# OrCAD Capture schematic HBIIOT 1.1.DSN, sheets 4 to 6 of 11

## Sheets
4 PCIe, M.2, RTC: size C; title: PCIE, M.2, RTC, IR
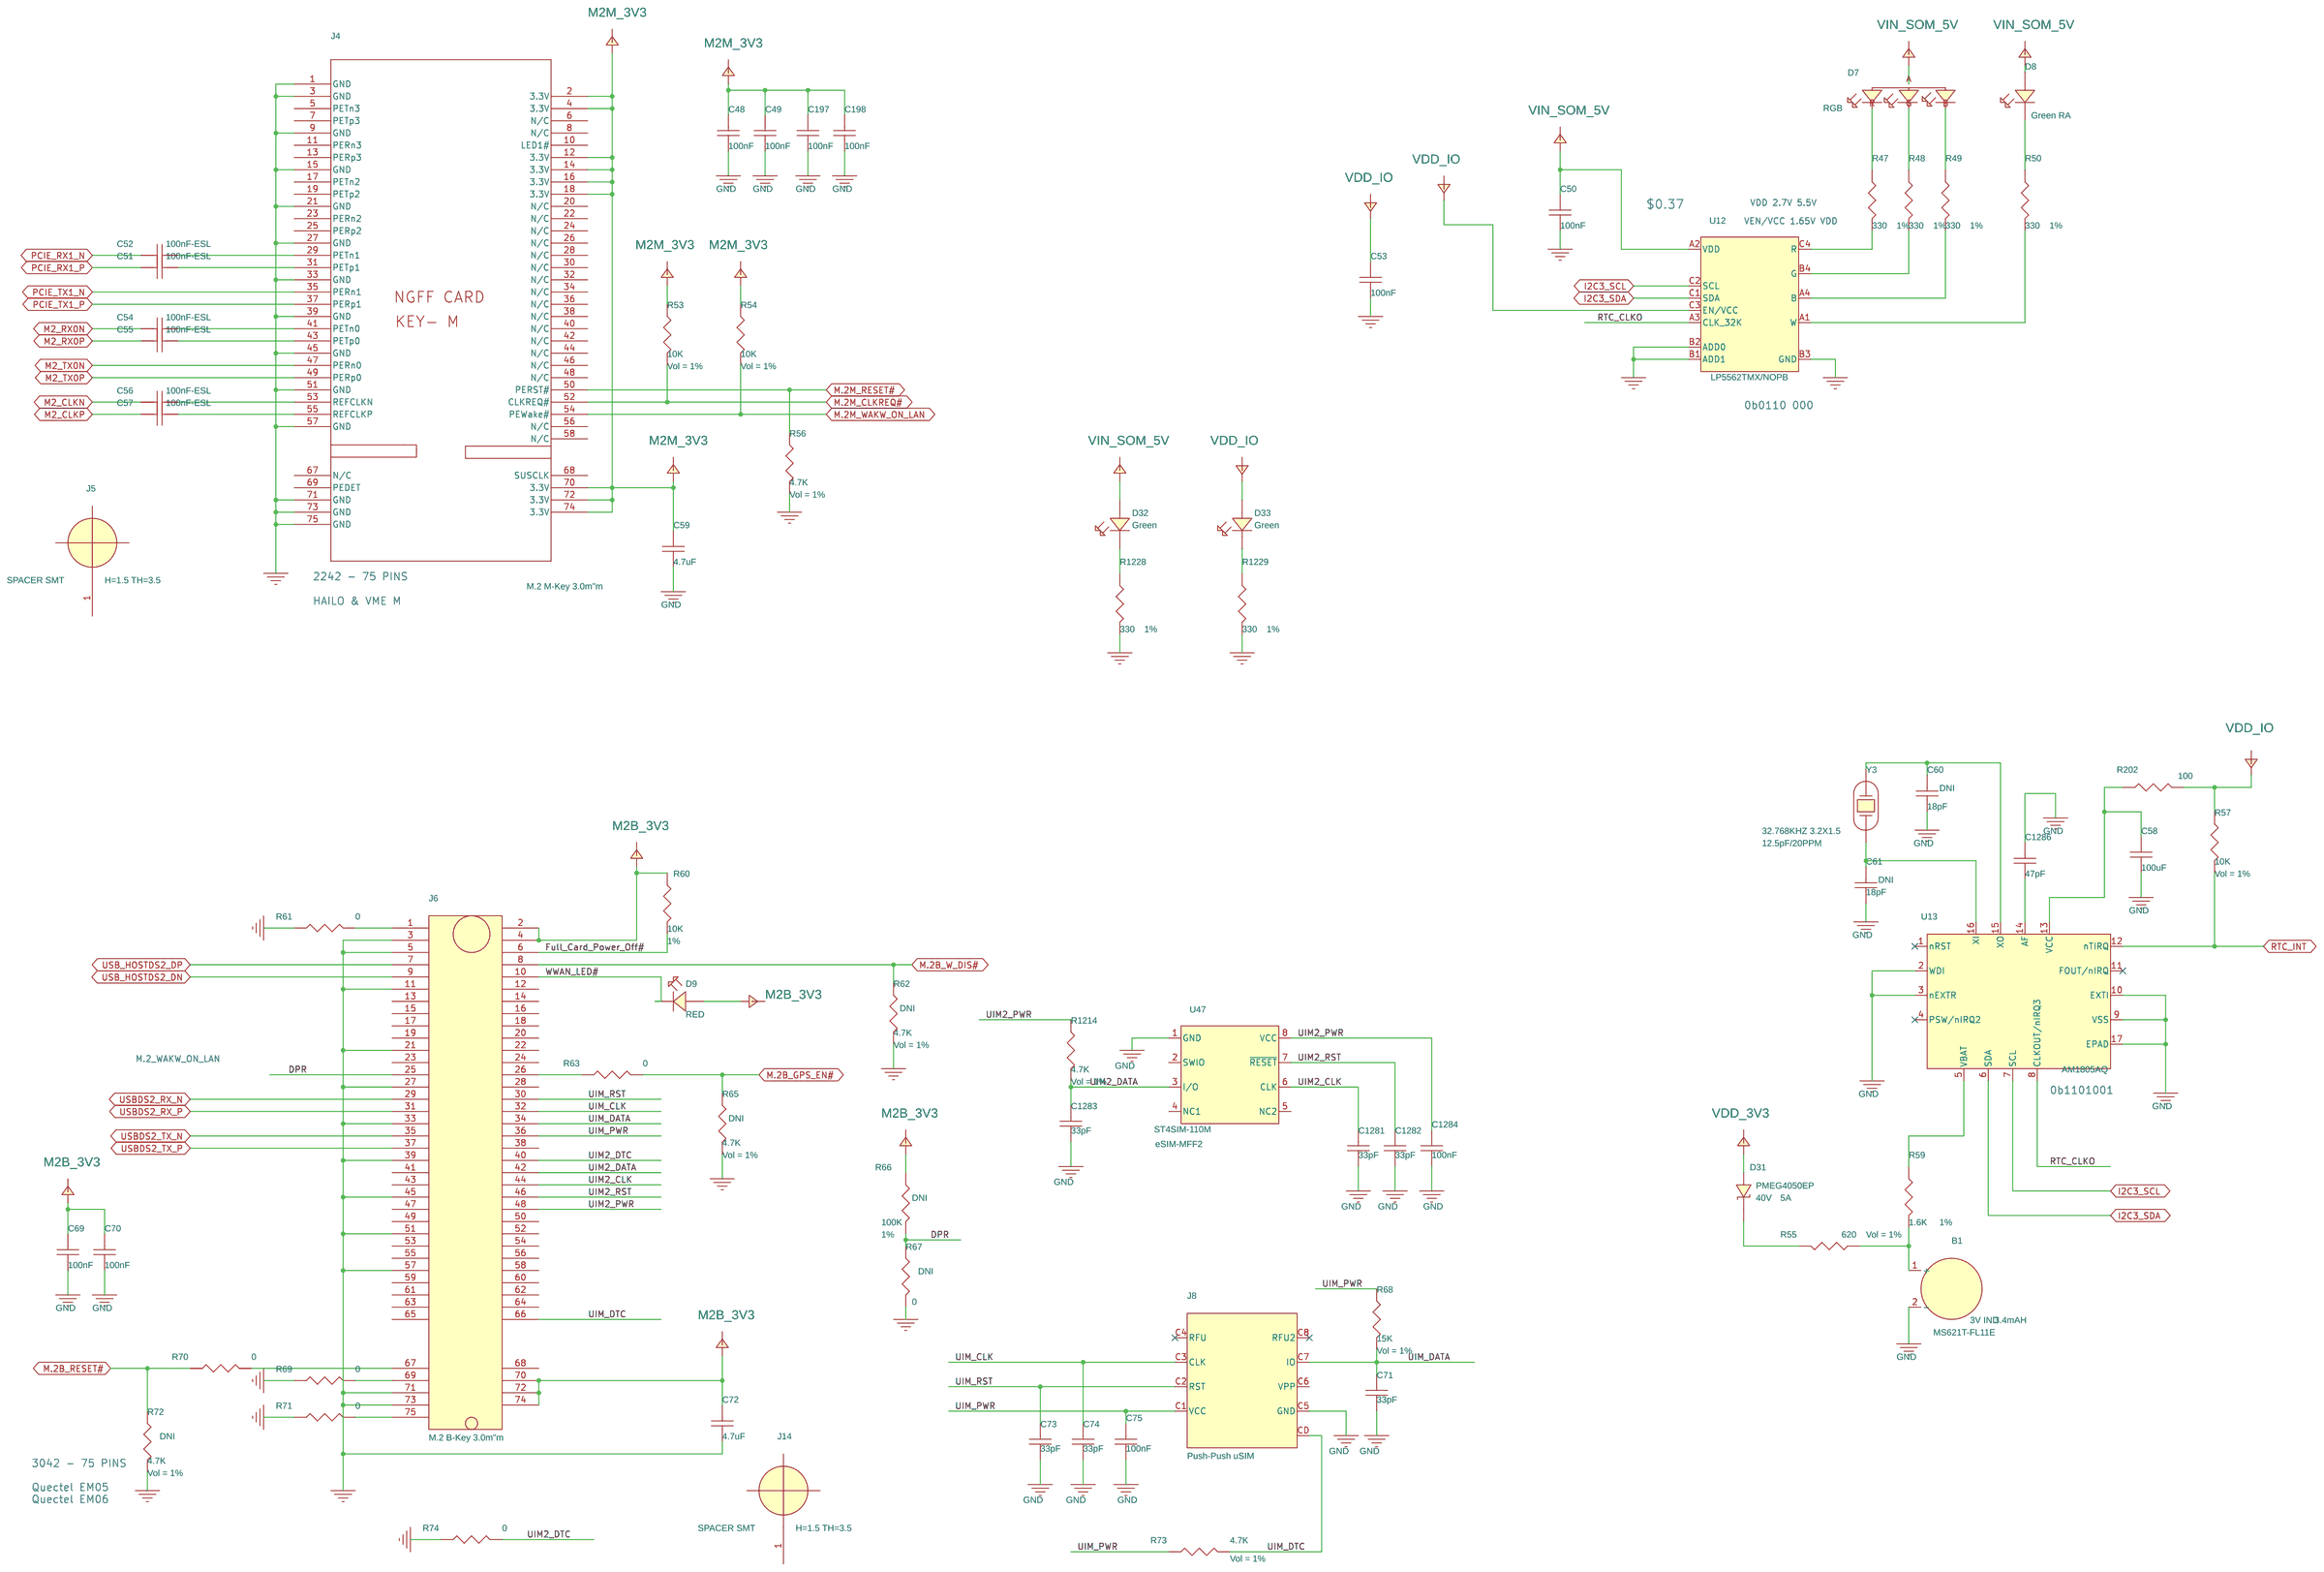
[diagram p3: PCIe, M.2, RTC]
5 Ethernet: size C; title: ETHERNET; rev: 2.4.0
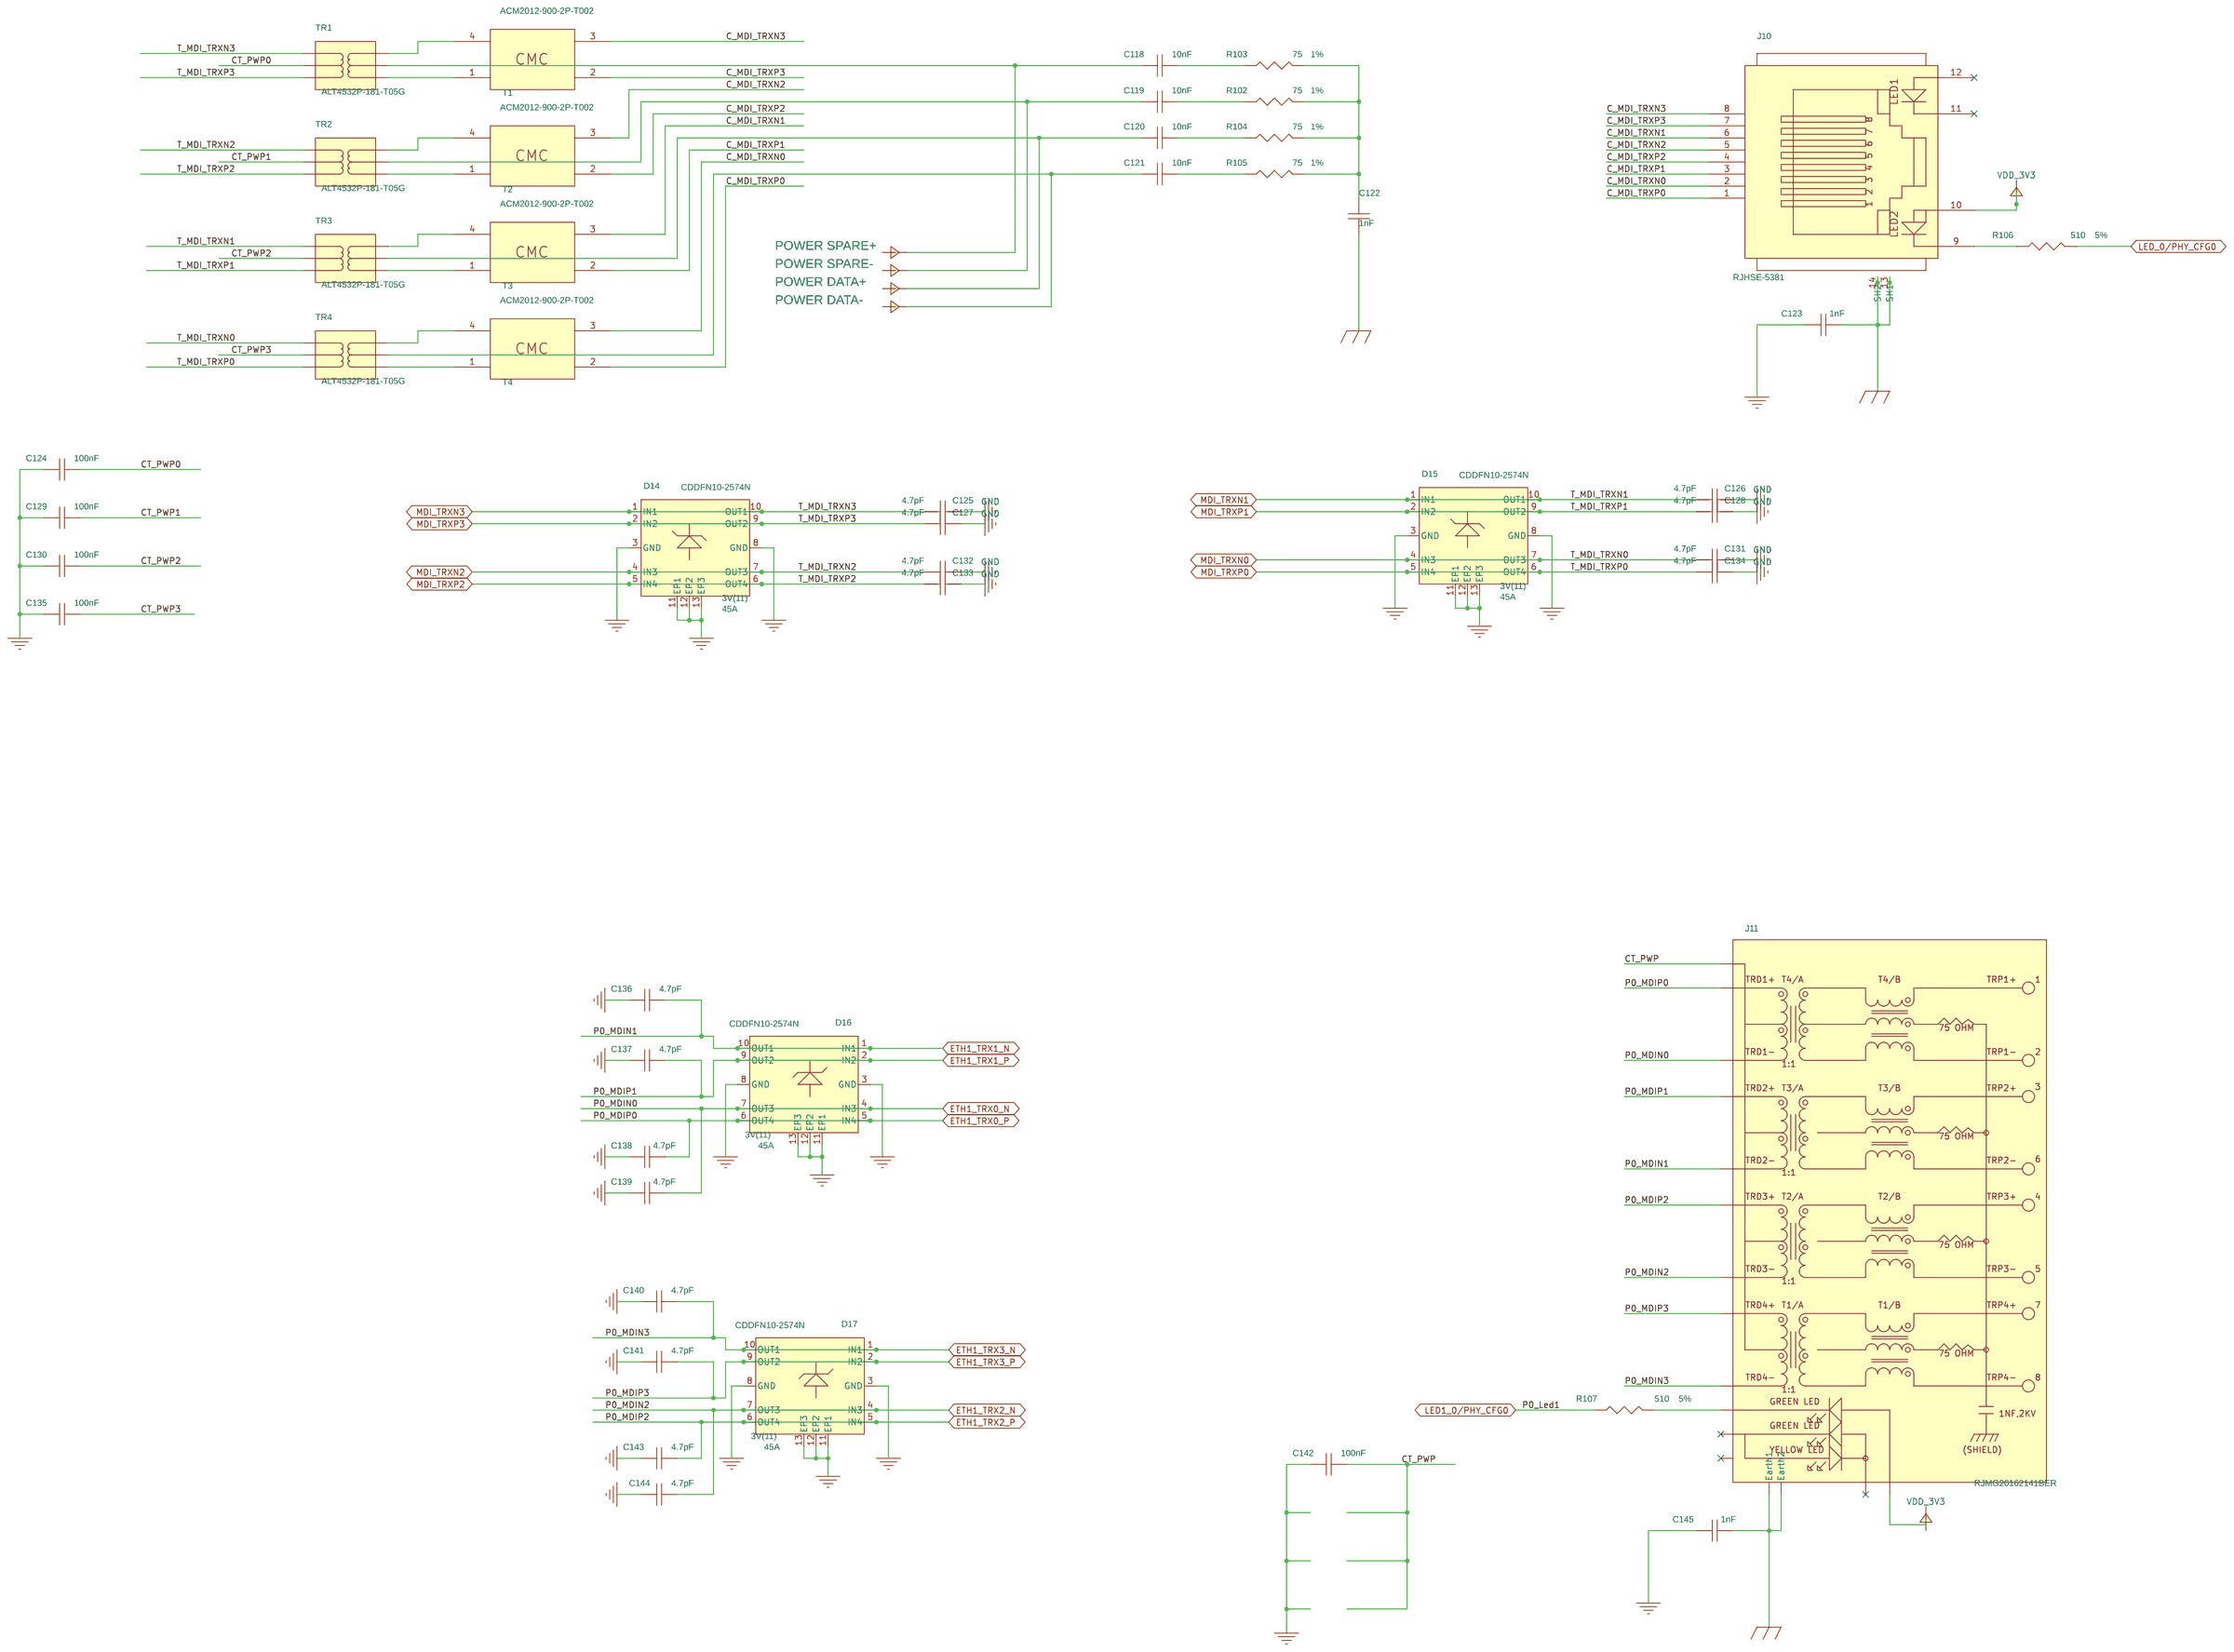
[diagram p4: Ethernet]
6 B-t-B Connectors: size D; title: B-T-B CONNECTORS; rev: 2.4.0
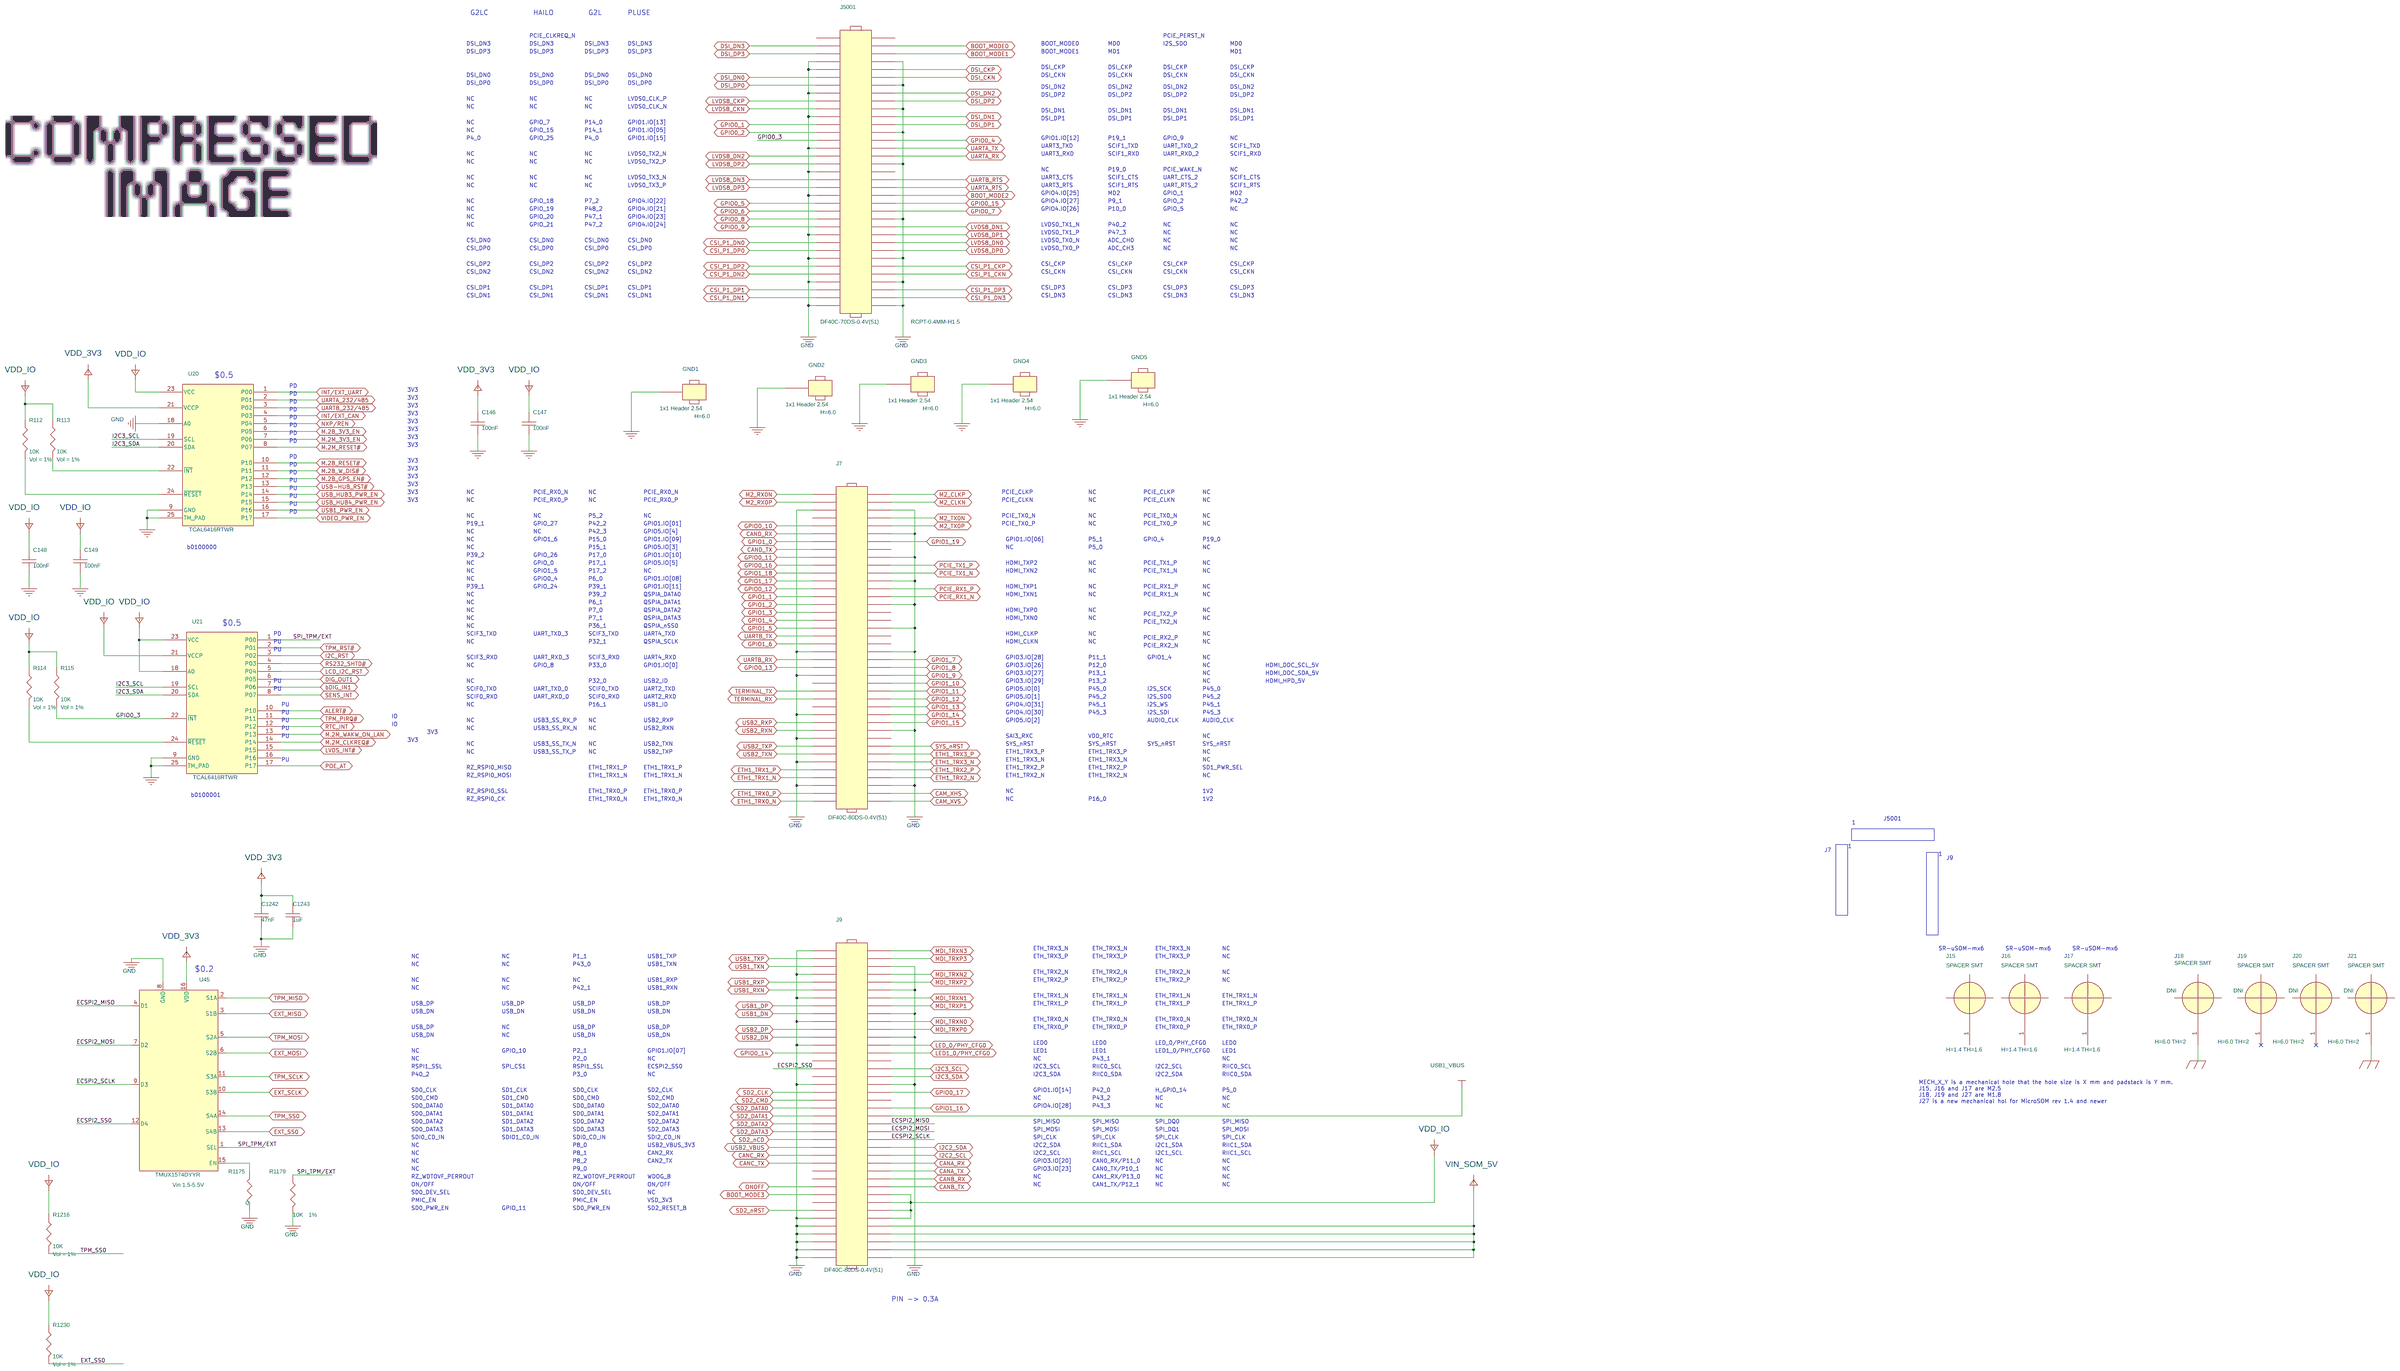
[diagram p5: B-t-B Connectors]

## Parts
sheet B-t-B Connectors
C146  100nF  [C0402]
C147  100nF  [C0402]
C148  100nF  [C0402]
C149  100nF  [C0402]
C1242  47nF  [C0402]
C1243  1uF  [C0402]
GND1  1x1 Header 2.54  [CH31012V200-NH]
GND2  1x1 Header 2.54  [CH31012V200-NH]
GND3  1x1 Header 2.54  [CH31012V200-NH]
GND4  1x1 Header 2.54  [CH31012V200-NH]
GND5  1x1 Header 2.54  [CH31012V200-NH]
J7  DF40C-80DS-0.4V(51)  [DF40C-80DS-0.4V(51)]
J9  DF40C-80DS-0.4V(51)  [DF40C-80DS-0.4V(51)]
J15  SPACER SMT
J16  SPACER SMT
J17  SPACER SMT
J18  SPACER SMT
J19  SPACER SMT
J20  SPACER SMT
J21  SPACER SMT
J5001  DF40C-70DS-0.4V(51)  [DF40C-70DS-0.4V(51)]
R112  10K  [R0402]
R113  10K  [R0402]
R114  10K  [R0402]
R115  10K  [R0402]
R1175  0  [R0402]
R1179  10K  [R0402]
R1216  10K  [R0402]
R1230  10K  [R0402]
U20  TCAL6416RTWR  [TCAL6416RTWR]
U21  TCAL6416RTWR  [TCAL6416RTWR]
U45  TMUX1574DYYR  [TMUX1574DYYR]
sheet Ethernet
C118  10nF  [C0402]
C119  10nF  [C0402]
C120  10nF  [C0402]
C121  10nF  [C0402]
C122  1nF  [C1206]
C123  1nF  [C1206]
C124  100nF  [C0402]
C125  4.7pF  [C0402]
C126  4.7pF  [C0402]
C127  4.7pF  [C0402]
C128  4.7pF  [C0402]
C129  100nF  [C0402]
C130  100nF  [C0402]
C131  4.7pF  [C0402]
C132  4.7pF  [C0402]
C133  4.7pF  [C0402]
C134  4.7pF  [C0402]
C135  100nF  [C0402]
C136  4.7pF  [C0402]
C137  4.7pF  [C0402]
C138  4.7pF  [C0402]
C139  4.7pF  [C0402]
C140  4.7pF  [C0402]
C141  4.7pF  [C0402]
C142  100nF  [C0402]
C143  4.7pF  [C0402]
C144  4.7pF  [C0402]
C145  1nF  [C1206]
D14  CDDFN10-2574N  [CDDFN10-2574N]
D15  CDDFN10-2574N  [CDDFN10-2574N]
D16  CDDFN10-2574N  [CDDFN10-2574N]
D17  CDDFN10-2574N  [CDDFN10-2574N]
J10  RJHSE-5381  [RJHSE-5381]
J11  RJMG20162141BER  [RJMG20162141BER]
R102  75  [R0402]
R103  75  [R0402]
R104  75  [R0402]
R105  75  [R0402]
R106  510  [R0402]
R107  510  [R0402]
T1  ACM2012-900-2P-T002  [ACM2012-900-2P-T002]
T2  ACM2012-900-2P-T002  [ACM2012-900-2P-T002]
T3  ACM2012-900-2P-T002  [ACM2012-900-2P-T002]
T4  ACM2012-900-2P-T002  [ACM2012-900-2P-T002]
TR1  ALT4532P-181-T05G  [ALT4532P-181-T05G]
TR2  ALT4532P-181-T05G  [ALT4532P-181-T05G]
TR3  ALT4532P-181-T05G  [ALT4532P-181-T05G]
TR4  ALT4532P-181-T05G  [ALT4532P-181-T05G]
sheet PCIe, M.2, RTC
B1  MS621T-FL11E  [MS621T-FL11E]
C48  100nF  [C0402]
C49  100nF  [C0402]
C50  100nF  [C0402]
C51  100nF-ESL  [C0402]
C52  100nF-ESL  [C0402]
C53  100nF  [C0402]
C54  100nF-ESL  [C0402]
C55  100nF-ESL  [C0402]
C56  100nF-ESL  [C0402]
C57  100nF-ESL  [C0402]
C58  100uF  [C1210]
C59  4.7uF  [C0603]
C60  18pF  [C0402]
C61  18pF  [C0402]
C69  100nF  [C0402]
C70  100nF  [C0402]
C71  33pF  [C0402]
C72  4.7uF  [C0603]
C73  33pF  [C0402]
C74  33pF  [C0402]
C75  100nF  [C0402]
C197  100nF  [C0402]
C198  100nF  [C0402]
C1281  33pF  [C0402]
C1282  33pF  [C0402]
C1283  33pF  [C0402]
C1284  100nF  [C0402]
C1286  47pF  [C0402]
D7  RGB  [LRTBR48G]
D8  Green RA  [APA2106CGCK]
D9  RED  [1SA0603S11A0CB01]
D31  PMEG4050EP  [PMEG4050EP]
D32  Green  [1SA0603G32A0CB01]
D33  Green  [1SA0603G32A0CB01]
J4  M.2 M-Key 3.0m"m  [AS0BC21-S30BM-7H]
J5  SPACER SMT
J6  M.2 B-Key 3.0m"m  [AS0BC21-S30BB-7H]
J8  Push-Push uSIM  [SIM7100-6-1-15-00-A]
J14  SPACER SMT
R47  330  [R0402]
R48  330  [R0402]
R49  330  [R0402]
R50  330  [R0402]
R53  10K  [R0402]
R54  10K  [R0402]
R55  620  [R0402]
R56  4.7K  [R0402]
R57  10K  [R0402]
R59  1.6K  [R0402]
R60  10K  [R0402]
R61  0  [R0402]
R62  4.7K  [R0402]
R63  0  [R0402]
R65  4.7K  [R0402]
R66  100K  [R0402]
R67  0  [R0402]
R68  15K  [R0402]
R69  0  [R0402]
R70  0  [R0402]
R71  0  [R0402]
R72  4.7K  [R0402]
R73  4.7K  [R0402]
R74  0  [R0402]
R202  100  [R0603]
R1214  4.7K  [R0402]
R1228  330  [R0402]
R1229  330  [R0402]
U12  LP5562TMX/NOPB  [LP5562TMX/NOPB]
U13  AM1805AQ  [AM1805AQ]
U47  ST4SIM-110M  [ST4SIM-110M]
Y3  32.768KHZ 3.2X1.5  [NX3215SA32.768K-STD-MUA-4]

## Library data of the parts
C75 C146-C149 C1284 = CAP_NP1: CAP CER 0.1uF ±10% 16V X7R 0402; Digikey P/N: 1276-1001-1-ND; Manufacturer: Samsung Electro-Mechanics; Part Num#: CL05B104KO5NNNC; Rating: 16V; SolidRun P/N: CA20013; Vol: 10%
C1242 = CAP_NP1: CHIP CAP 47nF 6.3V 0402 X7R; Manufacturer: Samsung Electro-Mechanics; Part Num#: CL05B473MQQNNNE; Rating: 6.3V; SolidRun P/N: CA20012; Vol: 10%
C1243 = CAP_NP1: CAP CER 1uF ±10% 6.3V X7R 0402; Digikey P/N: 1276-1513-1-ND; Manufacturer: Samsung Electro-Mechanics; Part Num#: CL05B105KQ5NQNC; Rating: 6.3V; SolidRun P/N: CA20132; Vol: 10%
GND1-GND5 = J-HEADER-1x1: CH31 Series 2.54mm(.100") Single Row Pin Headers- 1 x 1 V TH; Manufacturer: cvilux; SolidRun P/N: CO00517; Vol: H=6.0; Datasheet: https://www.cvilux.com/uploads/catalog/p283%20CH31.pdf
J7 J9 = J-DF40C-80DS-0.4V(51): CONN RCPT 80POS 0.4MM SMD GOLD Without reinforcing metal fitting 1.5mm; Category : CON-HEADER; Digikey P/N: H11633TR-ND; Manufacturer: Hirose Electric Co Ltd; SolidRun P/N: CO00017; VOL: RCPT-0.4MM-H1.5; Datasheet: https://www.hirose.com/product/download/?distributor=digikey&type=2d&lang=en&num=DF40C-80DS-0.4V(51)
J15-J17 = SPACER_SMT: SPACER H=1.4MM  TH=1.6MM - Used as imx6-uSOM spacer; Category : MECH-SPACER; Manufacturer: A-Link; Part Num#: N0143416A; SolidRun P/N: MCH0007; Vol: H=1.4 TH=1.6; Datasheet: http://www.alink.com.tw/smt%20fastener%20standard%20parts.html
J18-J21 = SPACER_SMT: 6mm PCB spacer to enclsoure (used in HummingBoard); ASSEMBLY: DNI; BOM_IGNORE: TRUE; Category : MECH-SPACER; Digikey P/N: 732-7103-2-ND; Manufacturer: Wurth Elektronik; Part Num#: WE 977-406-024-3R; SolidRun P/N: MCH0009; Vol: H=6.0 TH=2; Datasheet: http://katalog.we-online.de/em/datasheet/9774060243R.pdf
J5001 = J-DF40C-70DS-0.4V(51): CONN RCPT 70POS 0.4MM SMD GOLD Without reinforcing metal fitting 1.5 mm; Category : CON-HEADER; Digikey P/N: H11631TR-ND; Manufacturer: Hirose Electric Co Ltd; SolidRun P/N: CO00511; VOL: RCPT-0.4MM-H1.5; Datasheet: https://www.hirose.com/product/download/?distributor=digikey&type=2d&lang=en&num=DF40C-70DS-0.4V(51)
R53 R54 R57 R112-R115 R1216 R1230 = RES1: RES SMD 10K OHM 1% 1/16W 0402; Digikey P/N: 311-10.0KLRCT-ND; Manufacturer: YAGEO; Part Num#: RC0402FR-0710KL; Rating: 1/16W; SolidRun P/N: RE20013; Vol: 1%
R1175 = RES1: RES SMD 0 OHM JUMPER 1/16W 0402; Digikey P/N: 311-0.0JRCT-ND; Manufacturer: YAGEO; Part Num#: RC0402JR-070RL; Rating: 1/16W; SolidRun P/N: RE20009
R60 R1179 = RES1: RES SMD 10K OHM 1% 1/16W 0402; Category : Resistors (Size: 0402); Digikey P/N: 311-10.0KLRCT-ND; Manufacturer: YAGEO; Part Num#: RC0402FR-0710KL; Rating: 1/16W; SolidRun P/N: RE20013; Vol: 1%
U20 U21 = IC-TCAL6416-WQFN: I/O Expander 16 I²C 100 kHz 24-WQFN (4x4), voltage trans, Open Drain/Push/Pull; Digikey P/N: 296-TCAL6416RTWRTR-ND; Manufacturer: Texas Instruments; SolidRun P/N: IC01927; Datasheet: https://www.ti.com/lit/ds/symlink/tcal6416.pdf
U45 = IC-TMUX1574DYYR: 4 Circuit IC Switch 2:1 4.5Ohm 16-SOT-23-THIN; Digikey P/N: 296-TMUX1574DYYRTR-ND; Manufacturer: Texas Instruments; SolidRun P/N: IC01637; Vol: Vin 1.5-5.5V; Datasheet: https://www.ti.com/general/docs/suppproductinfo.tsp?distId=10&gotoUrl=https%3A%2F%2Fwww.ti.com%2Flit%2Fgpn%2Ftmux1574
C118-C121 = CAP_NP1: CAP CER 10000PF 100V X7R 0402; Category : Capacitors (Size: 0402); Digikey P/N: 13-CC0402KRX7R0BB103TR-ND; Manufacturer: YAGEO; Part Num#: CC0402KRX7R0BB103; Rating: 100V; SolidRun P/N: CA20837; Vol: 10%
C122 C123 C145 = CAP_NP1: CAP CER 1nF ±10% 1KV X7R 1206; Category : Capacitors (Size: 1206); Digikey P/N: 490-3494-2-ND; Manufacturer: Murata Electronics North America; Part Num#: GRM31BR73A102KW01L; Rating: 1KV; SolidRun P/N: CA50002; Vol: 10%
C124 C129 C130 C135 C142 = CAP_NP1: CAP CER 0.1uF ±10% 50V X7R 0402; Category : Capacitors (Size: 0402); Digikey P/N: 490-10700-1-ND; Manufacturer: Murata Electronics North America; Part Num#: GRM155R71H104KE14D; Rating: 50V; SolidRun P/N: CA20147; Vol: 10%
C125-C128 C131-C134 C136-C141 C143 C144 = CAP_NP1: CAP CER 4.7pF ±0.05pF 50V C0G/NP0 0402; Category : Capacitors (Size: 0402); Digikey P/N: 311-1033-1-ND; Manufacturer: Murata Electronics North America; Part Num#: GJM1555C1H4R7WB01D; Rating: 50V; SolidRun P/N: CA20807; Vol: 1%
D14-D17 = D-CDDFN10-2574N: TVS Diode Array, 4 Channel, Ipp=45A, Vclump=11V, 1.7pF@1MHz, 10-DFN (3x2), -55°C ~ 85°C (TA); Category: DI-TVS; Digikey P/N: CDDFN10-2574NCT-ND; Manufacturer: Bourns Inc.; Rating: 45A; SolidRun P/N: DI00271; Vol: 3V(11); Datasheet: https://www.bourns.com/docs/product-datasheets/cddfn10-2574n.pdf
J10 = J-RJHSE538x: CONN MOD JACK 8P8C R/A SHIELDED; Category : CON-ETH/RJ; Digikey P/N: RJHSE-5381-ND; Manufacturer: Amphenol Commercial Products; SolidRun P/N: CO00654; VOL: JACK 8P8C R/A SHIELDED; Datasheet: https://www.amphenolcanada.com/ProductSearch/drawings/AC/RJHSE538X.pdf
J11 = J-RJMG20162141BER-FCI: CONN MAGJACK 1PORT 1000 BASE-T; Category : CON-ETH/RJ; Digikey P/N: RJMG20162141BER-ND; Manufacturer: Amphenol Commercial Products; SolidRun P/N: CO00673; Vol: MAGJACK; Datasheet: https://www.amphenolcanada.com/ProductSearch/Drawings/AC/RJMG20162141BER.PDF
R102-R105 = RES1: RES SMD 75 OHM 1% 1/16W 0402; Category : Resistors (Size: 0402); Digikey P/N: 311-75.0LRCT-ND; Manufacturer: YAGEO; Part Num#: RC0402FR-0775RL; Rating: 1/16W; SolidRun P/N: RE20401; Vol: 1%
R106 R107 = RES1: RES SMD 510 OHM 5% 1/16W 0402; Category : Resistors (Size: 0402); Digikey P/N: 311-510JRCT-ND; Manufacturer: YAGEO; Part Num#: RC0402JR-07510RL; Rating: 1/16W; SolidRun P/N: RE20022; Vol: 5%
T1-T4 = CMC: 2 Line Common Mode Choke Surface Mount 90 Ohms @ 100MHz 400mA DCR 190mOhm; Digikey P/N: 445-2207-2-ND; Manufacturer: TDK Corporation; Rating: 0.4A; SolidRun P/N: IN00162; Vol: 90Ohm/100M; Datasheet: https://product.tdk.com/info/en/catalog/datasheets/cmf_commercial_signal_acm2012_en.pdf?ref_disty=digikey
TR1-TR4 = ALT4532M: PULSE TRANSFORMERS FOR LAN INTER, 180µH LAN Pulse Transformer 1CT:1CT Surface Mount POE+ suppport; Digikey P/N: 445-175377-2-ND; Manufacturer: TDK Corporation; SolidRun P/N: IC01873; Vol: POE+; Datasheet: https://product.tdk.com/en/system/files?file=dam/doc/product/transformer/transformer/lan/catalog/trans_alt4532p_en.pdf
B1 = BAT-MS621FE: Coin, 6.8mm 3 V Lithium Battery Rechargeable (Secondary) 3mAh IND (Was MS614SE FL28E); Category : Battery-RCH; Digikey P/N: 728-1080-ND; Manufacturer: Seiko Instruments; Rating: 3.4mAH; SolidRun P/N: BT00007; Vol: 3V IND; Datasheet: https://www.seiko-instruments.de/fileadmin/Editors/COMP/PDF/MicroBattery_catalogue_E_2018A_forWeb.pdf
C48 C49 C69 C70 C197 C198 = CAP_NP1: CAP CER 0.1uF ±10% 16V X7R 0402; Category : Capacitors (Size: 0603); Digikey P/N: 1276-1001-1-ND; Manufacturer: Samsung Electro-Mechanics; Part Num#: CL05B104KO5NNNC; Rating: 16V; SolidRun P/N: CA20013; Vol: 10%
C50 C53 = CAP_NP1: CAP CER 0.1uF ±10% 16V X7R 0402; Category : Capacitors (Size: 0402); Digikey P/N: 1276-1001-1-ND; Manufacturer: Samsung Electro-Mechanics; Part Num#: CL05B104KO5NNNC; Rating: 16V; SolidRun P/N: CA20013; Vol: 10%
C51 C52 C54-C57 = CAP_NP1: CAP CER 0.1uF ±10% 25V X7R 0402; Category : Capacitors (Size: 0402); Manufacturer: CAPAX; Part Num#: 0402X104K250SNT; Rating: 25V; SolidRun P/N: CA20090; Vol: 10%
C58 = CAP_NP1: CAP CER 100uF ±20% 16V X5R 1210; Category : Capacitors (Size: 0603); Digikey P/N: 311-2052-1-ND; Manufacturer: YAGEO; Part Num#: CC1210MKX5R7BB107; Rating: 16V; SolidRun P/N: CA60008; Vol: 20%
C59 C72 = CAP_NP1: CAP CER 4.7uF ±10% 6.3V X5R; Category : Capacitors (Size: 0603); Digikey P/N: 1276-1045-2-ND; Manufacturer: Samsung Electro-Mechanics; Part Num#: CL10A475KQ8NNNC; Rating: 6.3V; SolidRun P/N: CA30003; Vol: 10%
C60 C61 = CAP_NP1: CAP CER 18pF ±1% 50V C0G/NPO 0402; ASSEMBLY: DNI; BOM_IGNORE: TRUE; Category : Capacitors (Size: 0402); Digikey P/N: 311-1643-1-ND; Manufacturer: YAGEO; Part Num#: CC0402FRNPO9BN180; Rating: 50V; SolidRun P/N: CA20017; Vol: 1%
C71 C73 C74 C1281-C1283 = CAP_NP1: CAP CER 33pF ±5% 50V C0G/NP0 0402; Digikey P/N: 490-3220-1-ND; Manufacturer: Murata Electronics North America; Part Num#: GRM1555C1H330JZ01D; Rating: 50V; SolidRun P/N: CA20135; Vol: 5%
C1286 = CAP_NP1: CAP CER 47pF ±5% 50V C0G/NP0 0402; Category : Capacitors (Size: 0402); Digikey P/N: 490-1287-6-ND; Manufacturer: Murata Electronics North America; Part Num#: GRM1555C1H470JZ01D; Rating: 50V; SolidRun P/N: CA20144; Vol: 5%
D7 = LED-RGB: Red, Green, Blue (RGB) 623nm Red, 530nm Green, 471nm Blue LED Indication - Discrete 1.95V Red, 2.7V Green, 2.7V Blue 0404 (1010 Metric); Digikey P/N: 475-3483-2-ND; Manufacturer: OSRAM Opto Semiconductors Inc.; Part Num#: LRTB R48G-P9Q7-1+R7S5-26+N5P-68-ZB; Rating: 0.01/0.005/0.005A; SolidRun P/N: DI00259; Vol: 1.95/2.7/2.7; Datasheet: https://dammedia.osram.info/media/resource/hires/osram-dam-4307982/LRTB%20R48G.pdf
D8 = LED: LED 2.1X0.6MM 570NM GRN RA SMD; Category: DI-LED; Digikey P/N: 754-1057-2-ND; Manufacturer: Kingbright Corp; Rating: 0.02A; SolidRun P/N: DI00250; Vol: 2.1V; Datasheet: http://www.kingbrightusa.com/images/catalog/SPEC/APA2106CGCK.pdf
D9 = LED: Indication LED 0603 - Red; Category : DI-LED; Manufacturer: BRIGHTEK; Rating: 0.02A; SolidRun P/N: DI00007; Vol: 2V
D31 = Diode-STK-OLD: DIODE SCHOTTKY 40V 5A CFP5; Digikey P/N: 1727-5842-2-ND; Manufacturer: Nexperia USA Inc.; Rating: 5A; SolidRun P/N: DI00286; Vol: 40V; Datasheet: https://assets.nexperia.com/documents/data-sheet/PMEG4050EP.pdf
D32 D33 = LED: Indication LED 0603 - Green; Manufacturer: BRIGHTEK; Rating: 0.02A; SolidRun P/N: DI00008; Vol: 2V
J4 = M-NGFF_M.2_KEY_M: NGFF M.2 SSD M-Key 3.0 m"m connector; Manufacturer: Foxconn; SolidRun P/N: CO00514; Datasheet: http://www.fit-foxconn.com/Product/ProductDetail?topClassID=&&PN=AS0BC21-S30BM-7H
J5 J14 = SPACER_SMT: 1.5mm metal spacer for M.2.5 connector 3.5mm / 5.1mm (3.7mm / 6.0mm hole); Category: MECH-SPACER; Category : MECHANICAL PARTS; Digikey P/N: 732-7068-2-ND; Manufacturer: Wurth Elektronik; Part Num#: WE 977-401-515-1R; SolidRun P/N: MCH0008; Vol: H=1.5 TH=3.5; Datasheet: http://katalog.we-online.de/em/datasheet/9774015151R.pdf
J6 = M-NGFF_M.2: NGFF M.2 SSD connector with 2242 matching hole - 3.0H Key B; Category: CON-PCIe/SATA/M.2; Category : CON-PCIe/SATA/M.2; Manufacturer: Foxconn; SolidRun P/N: CO00595; Datasheet: http://www.fit-foxconn.com/Product/ProductDetail?topClassID=&&PN=AS0BC21-S30BB-7H
J8 = J-uSIM_CARD_HOLDER_x_8: Micro SIM Card Connector - Push-Push Type 6 or 8 Pin, SMT, 1.50mm Profile (6-pin); Digikey P/N: 2073-SIM7100-6-1-15-00-ATR-ND; Manufacturer: GCT; SolidRun P/N: CO00569; Datasheet: https://gct.co/files/drawings/sim7100.pdf
R47-R50 R1228 R1229 = RES1: RES SMD 330 OHM 1% 1/16W 0402; Category : Resistors (Size: 0402); Digikey P/N: 311-330LRCT-ND; Manufacturer: YAGEO; Part Num#: RC0402FR-07330RL; Rating: 1/16W; SolidRun P/N: RE20209; Vol: 1%
R55 = RES1: RES SMD 620 OHM 1% 1/16W 0402; Digikey P/N: 311-620LRCT-ND; Manufacturer: YAGEO; Part Num#: RC0402FR-07620RL; Rating: 1/16W; SolidRun P/N: RE20403; Vol: 1%
R56 R1214 = RES1: RES SMD 4.7K OHM 1% 1/16W 0402; Digikey P/N: 311-4.7KLRCT-ND; Manufacturer: YAGEO; Part Num#: RC0402FR-074K7L; Rating: 1/16W; SolidRun P/N: RE20497; Vol: 1%
R59 = RES1: RES SMD 1.6K OHM 1% 1/16W 0402; Category : Resistors (Size: 0402); Digikey P/N: YAG3045CT-ND; Manufacturer: YAGEO; Part Num#: RC0402FR-071K6L; Rating: 1/16W; SolidRun P/N: RE20030; Vol: 1%
R61 R63 R69-R71 R74 = RES1: RES SMD 0 OHM JUMPER 1/16W 0402; Category : Resistors (Size: 0402); Digikey P/N: 311-0.0JRCT-ND; Manufacturer: YAGEO; Part Num#: RC0402JR-070RL; Rating: 1/16W; SolidRun P/N: RE20009
R62 R65 R72 = RES1: RES SMD 4.7K OHM 1% 1/16W 0402; ASSEMBLY: DNI; BOM_IGNORE: TRUE; Digikey P/N: 311-4.7KLRCT-ND; Manufacturer: YAGEO; Part Num#: RC0402FR-074K7L; Rating: 1/16W; SolidRun P/N: RE20497; Vol: 1%
R66 = RES1: RES SMD 100K OHM 1% 1/16W 0402; ASSEMBLY: DNI; BOM_IGNORE: TRUE; Category : Resistors (Size: 0402); Digikey P/N: 311-100KLRCT-ND; Manufacturer: YAGEO; Part Num#: RC0402FR-07100KL; Rating: 1/16W; SolidRun P/N: RE20482; Vol: 1%
R67 = RES1: RES SMD 0 OHM JUMPER 1/16W 0402; ASSEMBLY: DNI; BOM_IGNORE: TRUE; Category : Resistors (Size: 0402); Digikey P/N: 311-0.0JRCT-ND; Manufacturer: YAGEO; Part Num#: RC0402JR-070RL; Rating: 1/16W; SolidRun P/N: RE20009
R68 = RES1: RES SMD 15K OHM 1% 1/16W 0402; Digikey P/N: 311-15.0KLRCT-ND; Manufacturer: YAGEO; Part Num#: RC0402FR-0715KL; Rating: 1/16W; SolidRun P/N: RE20100; Vol: 1%
R73 = RES1: RES SMD 4.7K OHM 1% 1/16W 0402; Category : Resistors (Size: 0402); Digikey P/N: 311-4.7KLRCT-ND; Manufacturer: YAGEO; Part Num#: RC0402FR-074K7L; Rating: 1/16W; SolidRun P/N: RE20497; Vol: 1%
R202 = RES1: RES SMD 100 OHM 5% 1/4W 0603; Digikey P/N: RHM100DTR-ND; Manufacturer: Rohm Semiconductor; Part Num#: ESR03EZPJ101; Rating: 1/4W; SolidRun P/N: RE30040; Vol: 5%
U12 = IC-LP5562: LED Driver IC 4 Output Linear I²C Dimming 25.5mA 12-DSBGA; Digikey P/N: 296-39061-2-ND; Manufacturer: Texas Instruments; SolidRun P/N: IC01926; Datasheet: https://www.ti.com/general/docs/suppproductinfo.tsp?distId=10&gotoUrl=https%3A%2F%2Fwww.ti.com%2Flit%2Fgpn%2Flp5562
U13 = IC-AM1805: REAL-TIME CLOCK WITH POWER MANAG; Category : IC-RTC; Digikey P/N: 1822-1006-2-ND; Manufacturer: Ambiq Micro, Inc.; SolidRun P/N: IC01186; Datasheet: http://ambiqmicro.com/wp-content/uploads/2016/11/am18x5_data_sheet_ds0003v1p2.pdf
U47 = IC-eSIM-MFF2: eSIM system-on-chip solution for secure M2M industrial applications; Manufacturer: STMicroelectronics; SolidRun P/N: IC01945; Vol: eSIM-MFF2; Datasheet: https://www.st.com/resource/en/data_brief/st4sim-110m.pdf
Y3 = XTAL-2P: XTAL 32.768KHZ 12.5PF 20PPM 3.2X1.5MM SM; Category : OC-CRYSTAL; Manufacturer: NDK; Rating: 12.5pF/20PPM; SolidRun P/N: OC00001; Datasheet: http://www.ndk.com/images/products/catalog/c_NX3215SA_e.pdf

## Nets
GND: B1.2(-) C48.2 C49.2 C50.2 C53.2 C58.2 C59.2 C60.2 C61.2 C69.2 C70.2 C71.2 C72.2 C73.2 C74.2 C75.2 C123.2 C124.1 C125.2 C126.2 C127.2 C128.2 C129.1 C130.1 C131.2 C132.2 C133.2 C134.2 C135.1 C136.2 C137.2 C138.2 C139.2 C140.2 C141.2 C142.1 C143.2 C144.2 C145.2 C146.2 C147.2 C148.2 C149.2 C197.2 C198.2 C1242.2 C1243.2 C1281.2 C1282.2 C1283.2 C1284.2 C1286.1 D14.3(GND) D14.8(GND) D14.11(EP1) D14.12(EP2) D14.13(EP3) D15.3(GND) D15.8(GND) D15.11(EP1) D15.12(EP2) D15.13(EP3) D16.3(GND) D16.8(GND) D16.11(EP1) D16.12(EP2) D16.13(EP3) D17.3(GND) D17.8(GND) D17.11(EP1) D17.12(EP2) D17.13(EP3) GND1.1 GND2.1 GND3.1 GND4.1 GND5.1 J4.1(GND) J4.3(GND) J4.9(GND) J4.15(GND) J4.21(GND) J4.27(GND) J4.33(GND) J4.39(GND) J4.45(GND) J4.51(GND) J4.57(GND) J4.71(GND) J4.73(GND) J4.75(GND) J6.3 J6.5 J6.11 J6.21 J6.27 J6.33 J6.39 J6.45 J6.51 J6.57 J6.71 J6.73 J7.5 J7.6 J7.11 J7.17 J7.23 J7.29 J7.35 J7.41 J7.42 J7.48 J7.58 J7.61 J7.64 J7.70 J7.75 J7.76 J8.C5(GND) J9.2 J9.5 J9.8 J9.11 J9.14 J9.17 J9.20 J9.23 J9.26 J9.35 J9.36 J9.70 J9.72 J9.74 J9.76 J9.78 J9.80 J5001.7 J5001.8 J5001.10 J5001.13 J5001.16 J5001.19 J5001.22 J5001.25 J5001.30 J5001.33 J5001.36 J5001.42 J5001.47 J5001.52 J5001.57 J5001.58 J5001.63 J5001.64 J5001.69 J5001.70 R56.2 R61.1 R62.2 R65.2 R67.2 R69.1 R71.1 R72.2 R74.1 R1175.2 R1179.2 R1228.2 R1229.2 U12.B1(ADD1) U12.B2(ADD0) U12.B3(GND) U13.2(WDI) U13.3(nEXTR) U13.9(VSS) U13.10(EXTI) U13.17(EPAD) U20.9(GND) U20.18(A0) U20.25(TM_PAD) U21.9(GND) U21.25(TM_PAD) U45.8(GND) U47.1(GND) ; also on sheet 1 2 3 7 8 9 11
GNDC: C122.2 C123.1 C145.1 J10.13(SH1) J10.14(SH2) J11.SH1(Earth1) J11.SH2(Earth2) J18.1 J21.1 ; also on sheet 2 3
VDD_3V3: C146.1 C1242.1 C1243.1 D31.2(ANODE) J10.10 J11.13 U20.21(VCCP) U45.16(VDD) ; also on sheet 1 2 3 7 8 11
VDD_IO: C53.1 C147.1 C148.1 C149.1 D33.A J9.63 J9.65 J9.67 J9.69 R57.1 R112.1 R113.1 R114.1 R115.1 R202.2 R1216.1 R1230.1 U12.C3(EN/VCC) U20.23(VCC) U21.18(A0) U21.21(VCCP) U21.23(VCC) ; also on sheet 1 2 7 8 9 11
ALERT#: U21.10(P10) ; also on sheet 9
bDIG_IN1: U21.7(P06) ; also on sheet 11
BOOT_MODE0: J5001.3 ; also on sheet 2
BOOT_MODE1: J5001.5 ; also on sheet 2
BOOT_MODE2: J5001.41 ; also on sheet 2
BOOT_MODE3: J9.64 ; also on sheet 2
C_MDI_TRXN0: J10.2 T4.3
C_MDI_TRXN1: J10.6 T3.3
C_MDI_TRXN2: J10.5 T2.3
C_MDI_TRXN3: J10.8 T1.3
C_MDI_TRXP0: J10.1 T4.2
C_MDI_TRXP1: J10.3 T3.2
C_MDI_TRXP2: J10.4 T2.2
C_MDI_TRXP3: J10.7 T1.2
CAM_XHS: J7.77 ; also on sheet 7
CAM_XVS: J7.79 ; also on sheet 7
CANA_RX: J9.55 ; also on sheet 11
CANA_TX: J9.57 ; also on sheet 11
CANB_RX: J9.59 ; also on sheet 11
CANB_TX: J9.61 ; also on sheet 11
CANC_RX: J9.54 ; also on sheet 11
CANC_TX: J9.56 ; also on sheet 11
CAND_RX: J7.12 ; also on sheet 11
CAND_TX: J7.16 ; also on sheet 11
CSI_P1_CKN: J5001.61 ; also on sheet 7
CSI_P1_CKP: J5001.59 ; also on sheet 7
CSI_P1_DN0: J5001.54 ; also on sheet 7
CSI_P1_DN1: J5001.68 ; also on sheet 7
CSI_P1_DN2: J5001.62 ; also on sheet 7
CSI_P1_DN3: J5001.67 ; also on sheet 7
CSI_P1_DP0: J5001.56 ; also on sheet 7
CSI_P1_DP1: J5001.66 ; also on sheet 7
CSI_P1_DP2: J5001.60 ; also on sheet 7
CSI_P1_DP3: J5001.65 ; also on sheet 7
CT_PWP: C142.2 J11.P2
CT_PWP0: C124.2 TR1.6
CT_PWP1: C129.2 TR2.6
CT_PWP2: C130.2 TR3.6
CT_PWP3: C135.2 TR4.6
DIG_OUT1: U21.6(P05) ; also on sheet 11
DPR: J6.25 R66.2 R67.1
DSI_CKN: J5001.11 ; also on sheet 7
DSI_CKP: J5001.9 ; also on sheet 7
DSI_DN0: J5001.12 ; also on sheet 7
DSI_DN1: J5001.21 ; also on sheet 7
DSI_DN2: J5001.15 ; also on sheet 7
DSI_DN3: J5001.4 ; also on sheet 7
DSI_DP0: J5001.14 ; also on sheet 7
DSI_DP1: J5001.23 ; also on sheet 7
DSI_DP2: J5001.17 ; also on sheet 7
DSI_DP3: J5001.6 ; also on sheet 7
ECSPI2_MISO: J9.45 U45.4(D1)
ECSPI2_MOSI: J9.47 U45.7(D2)
ECSPI2_SCLK: J9.49 U45.9(D3)
ECSPI2_SS0: J9.32 U45.12(D4)
ETH1_TRX0_N: C139.1 D16.4(IN3) D16.7(OUT3) J7.80 J11.P10
ETH1_TRX0_P: C138.1 D16.5(IN4) D16.6(OUT4) J7.78 J11.P9
ETH1_TRX1_N: C136.1 D16.1(IN1) D16.10(OUT1) J7.74 J11.P8
ETH1_TRX1_P: C137.1 D16.2(IN2) D16.9(OUT2) J7.72 J11.P7
ETH1_TRX2_N: C144.1 D17.4(IN3) D17.7(OUT3) J7.73 J11.P6
ETH1_TRX2_P: C143.1 D17.5(IN4) D17.6(OUT4) J7.71 J11.P5
ETH1_TRX3_N: C140.1 D17.1(IN1) D17.10(OUT1) J7.69 J11.P4
ETH1_TRX3_P: C141.1 D17.2(IN2) D17.9(OUT2) J7.67 J11.P3
EXT_MISO: U45.3(S1B) ; also on sheet 7
EXT_MOSI: U45.6(S2B) ; also on sheet 7
EXT_SCLK: U45.10(S3B) ; also on sheet 7
EXT_SS0: R1230.2 U45.13(S4B) ; also on sheet 7
Full_Card_Power_Off#: J6.6 R60.2
GPIO0_1: J5001.24 ; also on sheet 7
GPIO0_2: J5001.26 ; also on sheet 7
GPIO0_3: J5001.28 R115.2 U21.22(~{INT})
GPIO0_4: J5001.27 ; also on sheet 7
GPIO0_5: J5001.44 ; also on sheet 7
GPIO0_6: J5001.46 ; also on sheet 7
GPIO0_7: J5001.45 ; also on sheet 7
GPIO0_8: J5001.48 ; also on sheet 7
GPIO0_9: J5001.50 ; also on sheet 7
GPIO0_10: J7.10 ; also on sheet 7
GPIO0_11: J7.18 ; also on sheet 7
GPIO0_12: J7.26 ; also on sheet 7
GPIO0_13: J7.46 ; also on sheet 7
GPIO0_14: J9.28 ; also on sheet 7
GPIO0_15: J5001.43 ; also on sheet 7
GPIO0_16: J7.20 ; also on sheet 7
GPIO0_17: J9.37 ; also on sheet 7
GPIO1_0: J7.14 ; also on sheet 7
GPIO1_1: J7.28 ; also on sheet 7
GPIO1_2: J7.30 ; also on sheet 7
GPIO1_3: J7.32 ; also on sheet 7
GPIO1_4: J7.34 ; also on sheet 7
GPIO1_5: J7.36 ; also on sheet 7
GPIO1_6: J7.40 ; also on sheet 7
GPIO1_7: J7.43 ; also on sheet 7
GPIO1_8: J7.45 ; also on sheet 7
GPIO1_9: J7.47 ; also on sheet 7
GPIO1_10: J7.49 ; also on sheet 7
GPIO1_11: J7.51 ; also on sheet 7
GPIO1_12: J7.53 ; also on sheet 7
GPIO1_13: J7.55 ; also on sheet 7
GPIO1_14: J7.57 ; also on sheet 7
GPIO1_15: J7.59 ; also on sheet 7
GPIO1_16: J9.41 ; also on sheet 7
GPIO1_17: J7.24 ; also on sheet 7
GPIO1_18: J7.22 ; also on sheet 7
GPIO1_19: J7.13 ; also on sheet 7
I2C2_SCL: J9.53 ; also on sheet 3 7
I2C2_SDA: J9.51 ; also on sheet 3 7
I2C3_SCL: J9.31 U12.C2(SCL) U13.7(SCL) U20.19(SCL) U21.19(SCL) ; also on sheet 2 7 8 9
I2C3_SDA: J9.33 U12.C1(SDA) U13.6(SDA) U20.20(SDA) U21.20(SDA) ; also on sheet 2 7 8 9
I2C_RST: U21.3(P02) ; also on sheet 7
INT/EXT_CAN: U20.4(P03) ; also on sheet 11
INT/EXT_UART: U20.1(P00) ; also on sheet 11
LCD_I2C_RST: U21.5(P04) ; also on sheet 7
LED1_0/PHY_CFG0: J9.27 R107.1
LED_0/PHY_CFG0: J9.25 R106.2
LVDS8_CKN: J5001.20 ; also on sheet 7
LVDS8_CKP: J5001.18 ; also on sheet 7
LVDS8_DN0: J5001.53 ; also on sheet 7
LVDS8_DN1: J5001.49 ; also on sheet 7
LVDS8_DN2: J5001.32 ; also on sheet 7
LVDS8_DN3: J5001.38 ; also on sheet 7
LVDS8_DP0: J5001.55 ; also on sheet 7
LVDS8_DP1: J5001.51 ; also on sheet 7
LVDS8_DP2: J5001.34 ; also on sheet 7
LVDS8_DP3: J5001.40 ; also on sheet 7
LVDS_INT#: U21.15(P15) ; also on sheet 7
M2_CLKN: C56.1 J7.3
M2_CLKP: C57.1 J7.1
M2_RX0N: C54.1 J7.2
M2_RX0P: C55.1 J7.4
M2_TX0N: J4.47(PERn0) J7.7
M2_TX0P: J4.49(PERp0) J7.9
M2B_3V3: C69.1 C70.1 C72.1 D9.A J6.2 J6.4 J6.70 J6.72 J6.74 R60.1 R66.1 ; also on sheet 1
M2M_3V3: C48.1 C49.1 C59.1 C197.1 C198.1 J4.2(3.3V) J4.4(3.3V) J4.12(3.3V) J4.14(3.3V) J4.16(3.3V) J4.18(3.3V) J4.70(3.3V) J4.72(3.3V) J4.74(3.3V) R53.1 R54.1 ; also on sheet 1
M.2B_3V3_EN: U20.6(P05) ; also on sheet 1
M.2B_GPS_EN#: R63.2 R65.1 U20.12(P12)
M.2B_RESET#: R70.1 R72.1 U20.10(P10)
M.2B_W_DIS#: J6.8 R62.1 U20.11(P11)
M.2M_3V3_EN: U20.7(P06) ; also on sheet 1
M.2M_CLKREQ#: J4.52(CLKREQ#) R53.2 U21.14(P14)
M.2M_RESET#: J4.50(PERST#) R56.1 U20.8(P07)
M.2M_WAKW_ON_LAN: J4.54(PEWake#) R54.2 U21.13(P13)
MDI_TRXN0: C131.1 D15.4(IN3) D15.7(OUT3) J9.19 TR4.1
MDI_TRXN1: C126.1 D15.1(IN1) D15.10(OUT1) J9.13 TR3.1
MDI_TRXN2: C132.1 D14.4(IN3) D14.7(OUT3) J9.7 TR2.1
MDI_TRXN3: C125.1 D14.1(IN1) D14.10(OUT1) J9.1 TR1.1
MDI_TRXP0: C134.1 D15.5(IN4) D15.6(OUT4) J9.21 TR4.2
MDI_TRXP1: C128.1 D15.2(IN2) D15.9(OUT2) J9.15 TR3.2
MDI_TRXP2: C133.1 D14.5(IN4) D14.6(OUT4) J9.9 TR2.2
MDI_TRXP3: C127.1 D14.2(IN2) D14.9(OUT2) J9.3 TR1.2
NXP/REN: U20.5(P04) ; also on sheet 11
ONOFF: J9.62 ; also on sheet 2
PCIE_RX1_N: C52.1 J7.27
PCIE_RX1_P: C51.1 J7.25
PCIE_TX1_N: J4.35(PERn1) J7.21
PCIE_TX1_P: J4.37(PERp1) J7.19
POE_AT: U21.17(P17) ; also on sheet 1
Power Data+: C120.1 TR3.3 ; also on sheet 1
Power Data-: C121.1 TR4.3 ; also on sheet 1
Power Spare+: C118.1 TR1.3 ; also on sheet 1
Power Spare-: C119.1 TR2.3 ; also on sheet 1
RS232_SHTD#: U21.4(P03) ; also on sheet 11
RTC_CLKO: U12.A3(CLK_32K) U13.8(CLKOUT/nIRQ3)
RTC_INT: R57.2 U13.12(nTIRQ) U21.12(P12)
SD2_CLK: J9.38 ; also on sheet 2
SD2_CMD: J9.40 ; also on sheet 2
SD2_DATA0: J9.42 ; also on sheet 2
SD2_DATA1: J9.44 ; also on sheet 2
SD2_DATA2: J9.46 ; also on sheet 2
SD2_DATA3: J9.48 ; also on sheet 2
SD2_nCD: J9.50 ; also on sheet 2
SD2_nRST: J9.68 ; also on sheet 2
SENS_INT: U21.8(P07) ; also on sheet 8
SPI_TPM/EXT: R1179.1 U21.1(P00) U45.1(SEL)
SYS_nRST: J7.65 ; also on sheet 2
TERMINAL_RX: J7.54 ; also on sheet 2
TERMINAL_TX: J7.52 ; also on sheet 2
TPM_MISO: U45.2(S1A) ; also on sheet 2
TPM_MOSI: U45.5(S2A) ; also on sheet 2
TPM_PIRQ#: U21.11(P11) ; also on sheet 2
TPM_RST#: U21.2(P01) ; also on sheet 2
TPM_SCLK: U45.11(S3A) ; also on sheet 2
TPM_SS0: R1216.2 U45.14(S4A) ; also on sheet 2
UARTA_232/485: U20.2(P01) ; also on sheet 11
UARTA_RTS: J5001.39 ; also on sheet 7 11
UARTA_RX: J5001.31 ; also on sheet 11
UARTA_TX: J5001.29 ; also on sheet 11
UARTB_232/485: U20.3(P02) ; also on sheet 11
UARTB_RTS: J5001.37 ; also on sheet 7 11
UARTB_RX: J7.44 ; also on sheet 11
UARTB_TX: J7.38 ; also on sheet 11
UIM2_CLK: C1281.1 J6.44 U47.6(CLK)
UIM2_DATA: C1283.1 J6.42 R1214.2 U47.3(I/O)
UIM2_DTC: J6.40 R74.2
UIM2_PWR: C1284.1 J6.48 R1214.1 U47.8(VCC)
UIM2_RST: C1282.1 J6.46 U47.7(~{RESET})
UIM_CLK: C74.1 J6.32 J8.C3(CLK)
UIM_DATA: C71.1 J6.34 J8.C7(IO) R68.2
UIM_DTC: J6.66 J8.CD R73.2
UIM_PWR: C75.1 J6.36 J8.C1(VCC) R68.1 R73.1
UIM_RST: C73.1 J6.30 J8.C2(RST)
USB1_DN: J9.18 ; also on sheet 3
USB1_DP: J9.16 ; also on sheet 3
USB1_PWR_EN: U20.16(P16) ; also on sheet 3
USB1_RXN: J9.12 ; also on sheet 3
USB1_RXP: J9.10 ; also on sheet 3
USB1_TXN: J9.6 ; also on sheet 3
USB1_TXP: J9.4 ; also on sheet 3
USB1_VBUS: J9.43 ; also on sheet 3
USB2_DN: J9.24 ; also on sheet 3
USB2_DP: J9.22 ; also on sheet 3
USB2_RXN: J7.62 ; also on sheet 3
USB2_RXP: J7.60 ; also on sheet 3
USB2_TXN: J7.68 ; also on sheet 3
USB2_TXP: J7.66 ; also on sheet 3
USB2_VBUS: J9.52 ; also on sheet 3
USB-HUB_RST#: U20.13(P13) ; also on sheet 3
USB_5V0: C50.1 D7.A D8.A D32.A J9.71 J9.73 J9.75 J9.77 J9.79 U12.A2(VDD) ; also on sheet 1 3 7 11
USB_HOSTDS2_DN: J6.9 ; also on sheet 3
USB_HOSTDS2_DP: J6.7 ; also on sheet 3
USB_HUB3_PWR_EN: U20.14(P14) ; also on sheet 3
USB_HUB4_PWR_EN: U20.15(P15) ; also on sheet 3
USBDS2_RX_N: J6.29 ; also on sheet 3
USBDS2_RX_P: J6.31 ; also on sheet 3
USBDS2_TX_N: J6.35 ; also on sheet 3
USBDS2_TX_P: J6.37 ; also on sheet 3
VIDEO_PWR_EN: U20.17(P17) ; also on sheet 1
WWAN_LED#: D9.C J6.10
N949648: J11.14 R107.2
N18120079: J6.1 R61.2
N18120959: J6.69 R69.2
N18121129: J6.75 R71.2
N18121548: J6.26 R63.1
N18121564: J6.67 R70.2
N18446433: T1.4 TR1.5
N18446493: C118.2 R103.1
N18446495: C122.1 R102.2 R103.2 R104.2 R105.2
N18446501: T1.1 TR1.4
N18446555: C119.2 R102.1
N18446657: T2.4 TR2.5
N18446671: C120.2 R104.1
N18446738: T2.1 TR2.4
N18446750: C121.2 R105.1
N18446829: T3.4 TR3.5
N18446855: T3.1 TR3.4
N18446918: T4.4 TR4.5
N18446941: T4.1 TR4.4
N18447504: J10.9 R106.1
N18590703: C54.2 J4.41(PETn0)
N18590707: C55.2 J4.43(PETp0)
N18590807: C56.2 J4.53(REFCLKN)
N18590811: C57.2 J4.55(REFCLKP)
N18759599: D7.R R47.1
N18759601: D7.G R48.1
N18759603: D7.B R49.1
N18759605: D8.C R50.1
N18759711: R47.2 U12.C4(R)
N18759713: R48.2 U12.B4(G)
N18759715: R49.2 U12.A4(B)
N18759717: R50.2 U12.A1(W)
N18960531: R113.2 U20.22(~{INT})
N18960536: R112.2 U20.24(~{RESET})
N18961727: R114.2 U21.24(~{RESET})
N19529002: C52.2 J4.29(PETn1)
N19529051: C51.2 J4.31(PETp1)
N19565072: R1175.1 U45.15(EN)
N19725768: C60.1 U13.15(XO) Y3.2
N19725841: C58.1 R202.1 U13.13(VCC)
N19725861: C61.1 U13.16(XI) Y3.1
N19725923: C1286.2 U13.14(AF)
N19726053: R59.1 U13.5(VBAT)
N19726104: B1.1(+) R55.1 R59.2
N19730045: D31.1(CATHODE) R55.2
N20168326: D32.C R1228.1
N20168519: D33.C R1229.1

Not connected (* = marked no-connect by the designer): J4 5(PETn3) 6(N/C) 7(PETp3) 8(N/C) 10(LED1#) 11(PERn3) 13(PERp3) 17(PETn2) 19(PETp2) 20(N/C) 22(N/C) 23(PERn2) 24(N/C) 25(PERp2) 26(N/C) 28(N/C) 30(N/C) 32(N/C) 34(N/C) 36(N/C) 38(N/C) 40(N/C) 42(N/C) 44(N/C) 46(N/C) 48(N/C) 56(N/C) 58(N/C) 67(N/C) 68(SUSCLK) 69(PEDET); J5 1; J6 12 13 14 15 16 17 18 19 20 22 23 24 28 38 41 43 47 49 50 52 53 54 55 56 58 59 60 61 62 63 64 65 68; J7 8 15 31 33 37 39 50 56 63; J8 C4(RFU)* C6(VPP) C8(RFU2)*; J9 29 30 34 39 58 60 66; J10 11* 12*; J11 11* 12* P1*; J14 1; J15 1; J16 1; J17 1; J19 1*; J20 1*; J5001 1 2 35; U13 1(nRST)* 4(PSW/nIRQ2)* 11(FOUT/nIRQ)*; U21 16(P16); U47 2(SWIO) 4(NC1) 5(NC2)

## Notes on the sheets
sheet 4
- $0.37
- VDD 2.7V 5.5V
- VEN/VCC 1.65V VDD
- 0b0110 000
- 2242 - 75 PINS
- HAILO & VME M
- M.2_WAKW_ON_LAN
- 0b1101001
- 3042 - 75 PINS
  Quectel EM05
  Quectel EM06
sheet 6
- G2LC
- HAILO
- G2L
- PLUSE
- PCIE_CLKREQ_N
- PCIE_PERST_N
- DSI_DN3
- DSI_DN3
- DSI_DN3
- DSI_DN3
- BOOT_MODE0
- MD0
- I2S_SDO
- MD0
- DSI_DP3
- DSI_DP3
- DSI_DP3
- DSI_DP3
- BOOT_MODE1
- MD1
- MD1
- DSI_CKP
- DSI_CKP
- DSI_CKP
- DSI_CKP
- DSI_DN0
- DSI_DN0
- DSI_DN0
- DSI_DN0
- DSI_CKN
- DSI_CKN
- DSI_CKN
- DSI_CKN
- DSI_DP0
- DSI_DP0
- DSI_DP0
- DSI_DP0
- DSI_DN2
- DSI_DP2
- DSI_DN2
- DSI_DP2
- DSI_DN2
- DSI_DP2
- DSI_DN2
- DSI_DP2
- NC
- NC
- NC
- LVDS0_CLK_P
- NC
- NC
- NC
- LVDS0_CLK_N
- DSI_DN1
- DSI_DN1
- DSI_DN1
- DSI_DN1
- NC
- GPIO_7
- P14_0
- GPIO1.IO[13]
- DSI_DP1
- DSI_DP1
- DSI_DP1
- DSI_DP1
- NC
- GPIO_15
- P14_1
- GPIO1.IO[05]
- P4_0
- GPIO_25
- P4_0
- GPIO1.IO[15]
- GPIO1.IO[12]
- P19_1
- GPIO_9
- NC
- UART3_TXD
- SCIF1_TXD
- UART_TXD_2
- SCIF1_TXD
- NC
- NC
- NC
- LVDS0_TX2_N
- UART3_RXD
- SCIF1_RXD
- UART_RXD_2
- SCIF1_RXD
- NC
- NC
- NC
- LVDS0_TX2_P
- NC
- P19_0
- PCIE_WAKE_N
- NC
- NC
- NC
- NC
- LVDS0_TX3_N
- UART3_CTS
- SCIF1_CTS
- UART_CTS_2
- SCIF1_CTS
- NC
- NC
- NC
- LVDS0_TX3_P
- UART3_RTS
- SCIF1_RTS
- UART_RTS_2
- SCIF1_RTS
- GPIO4.IO[25]
- MD2
- GPIO_1
- MD2
- NC
- GPIO_18
- P7_2
- GPIO4.IO[22]
- GPIO4.IO[27]
- P9_1
- GPIO_2
- P42_2
- NC
- NC
- GPIO_19
- GPIO_20
- P47_1
- P48_2
- GPIO4.IO[21]
- GPIO4.IO[23]
- GPIO4.IO[26]
- P10_0
- GPIO_5
- NC
- NC
- GPIO_21
- P47_2
- GPIO4.IO[24]
- LVDS0_TX1_N
- P40_2
- NC
- NC
- LVDS0_TX1_P
- P47_3
- NC
- NC
- CSI_DN0
- CSI_DN0
- CSI_DN0
- CSI_DN0
- LVDS0_TX0_N
- ADC_CH0
- NC
- NC
- CSI_DP0
- CSI_DP0
- CSI_DP0
- CSI_DP0
- LVDS0_TX0_P
- ADC_CH3
- NC
- NC
- CSI_DN2
- CSI_DP2
- CSI_DN2
- CSI_DP2
- CSI_DN2
- CSI_DP2
- CSI_DN2
- CSI_DP2
- CSI_CKN
- CSI_CKP
- CSI_CKN
- CSI_CKP
- CSI_CKN
- CSI_CKP
- CSI_CKN
- CSI_CKP
- CSI_DP1
- CSI_DP1
- CSI_DP1
- CSI_DP1
- CSI_DP3
- CSI_DP3
- CSI_DP3
- CSI_DP3
- CSI_DN1
- CSI_DN1
- CSI_DN1
- CSI_DN1
- CSI_DN3
- CSI_DN3
- CSI_DN3
- CSI_DN3
- $0.5
- PD
- 3V3
- PD
- PD
- 3V3
- PD
- 3V3
- PD
- 3V3
- 3V3
- PD
- 3V3
- PD
- 3V3
- PD
- 3V3
- PD
- PD
- 3V3
- PD
- 3V3
- 3V3
- PU
- 3V3
- PU
- 3V3
- NC
- PCIE_RX0_N
- NC
- PCIE_RX0_N
- PCIE_CLKP
- NC
- PCIE_CLKP
- NC
- PU
- PU
- 3V3
- NC
- PCIE_RX0_P
- NC
- PCIE_RX0_P
- PCIE_CLKN
- NC
- PCIE_CLKN
- NC
- PD
- NC
- NC
- P5_2
- NC
- PCIE_TX0_N
- NC
- PCIE_TX0_N
- NC
- NC
- P19_1
- GPIO_27
- NC
- P42_2
- P42_3
- GPIO1.IO[01]
- GPIO5.IO[4]
- PCIE_TX0_P
- NC
- PCIE_TX0_P
- NC
- NC
- GPIO1_6
- P15_0
- GPIO1.IO[09]
- GPIO1.IO[06]
- P5_1
- GPIO_4
- P19_0
- b0100000
- NC
- P15_1
- GPIO5.IO[3]
- NC
- P5_0
- NC
- P39_2
- GPIO_26
- P17_0
- GPIO1.IO[10]
- NC
- GPIO_0
- P17_1
- GPIO5.IO[5]
- HDMI_TXP2
- NC
- PCIE_TX1_P
- NC
- NC
- NC
- GPIO0_4
- GPIO1_5
- P17_2
- P6_0
- GPIO1.IO[08]
- NC
- HDMI_TXN2
- NC
- PCIE_TX1_N
- NC
- P39_1
- GPIO_24
- P39_1
- GPIO1.IO[11]
- HDMI_TXP1
- NC
- PCIE_RX1_P
- NC
- NC
- P39_2
- QSPIA_DATA0
- HDMI_TXN1
- NC
- PCIE_RX1_N
- NC
- NC
- P6_1
- QSPIA_DATA1
- NC
- P7_0
- QSPIA_DATA2
- HDMI_TXP0
- NC
- PCIE_TX2_P
- NC
- $0.5
- NC
- P7_1
- QSPIA_DATA3
- HDMI_TXN0
- NC
- PCIE_TX2_N
- NC
- PD
- NC
- SCIF3_TXD
- UART_TXD_3
- P36_1
- SCIF3_TXD
- QSPIA_nSS0
- UART4_TXD
- HDMI_CLKP
- NC
- NC
- PU
- NC
- P32_1
- QSPIA_SCLK
- HDMI_CLKN
- NC
- PCIE_RX2_P
- NC
- PU
- PCIE_RX2_N
- SCIF3_RXD
- UART_RXD_3
- SCIF3_RXD
- UART4_RXD
- GPIO3.IO[28]
- P11_1
- GPIO1_4
- NC
- NC
- GPIO_8
- P33_0
- GPIO1.IO[0]
- GPIO3.IO[26]
- P12_0
- NC
- HDMI_DDC_SCL_5V
- PU
- NC
- P32_0
- USB2_ID
- GPIO3.IO[27]
- GPIO3.IO[29]
- P13_1
- P13_2
- NC
- NC
- HDMI_DDC_SDA_5V
- HDMI_HPD_5V
- PU
- SCIF0_TXD
- UART_TXD_0
- SCIF0_TXD
- UART2_TXD
- GPIO5.IO[0]
- P45_0
- I2S_SCK
- P45_0
- SCIF0_RXD
- UART_RXD_0
- SCIF0_RXD
- UART2_RXD
- GPIO5.IO[1]
- P45_2
- I2S_SDO
- P45_2
- PU
- NC
- P16_1
- USB1_ID
- GPIO4.IO[31]
- P45_1
- I2S_WS
- P45_1
- PU
- IO
- GPIO4.IO[30]
- P45_3
- I2S_SDI
- P45_3
- PU
- IO
- NC
- USB3_SS_RX_P
- NC
- USB2_RXP
- GPIO5.IO[2]
- AUDIO_CLK
- AUDIO_CLK
- PU
- PU
- 3V3
- NC
- USB3_SS_RX_N
- NC
- USB2_RXN
- SAI3_RXC
- VDD_RTC
- NC
- 3V3
- NC
- USB3_SS_TX_N
- NC
- USB2_TXN
- SYS_nRST
- SYS_nRST
- SYS_nRST
- SYS_nRST
- NC
- USB3_SS_TX_P
- NC
- USB2_TXP
- ETH1_TRX3_P
- ETH1_TRX3_P
- NC
- PU
- ETH1_TRX3_N
- ETH1_TRX3_N
- NC
- RZ_RSPI0_MISO
- ETH1_TRX1_P
- ETH1_TRX1_P
- ETH1_TRX2_P
- ETH1_TRX2_P
- SD1_PWR_SEL
- RZ_RSPI0_MOSI
- ETH1_TRX1_N
- ETH1_TRX1_N
- ETH1_TRX2_N
- ETH1_TRX2_N
- NC
- RZ_RSPI0_SSL
- ETH1_TRX0_P
- ETH1_TRX0_P
- NC
- 1V2
- b0100001
- RZ_RSPI0_CK
- ETH1_TRX0_N
- ETH1_TRX0_N
- NC
- P16_0
- 1V2
- J5001
- 1
- 1
- J7
- 1
- J9
- ETH_TRX3_N
- ETH_TRX3_N
- ETH_TRX3_N
- NC
- SR-uSOM-mx6
- SR-uSOM-mx6
- SR-uSOM-mx6
- NC
- NC
- P1_1
- USB1_TXP
- ETH_TRX3_P
- ETH_TRX3_P
- ETH_TRX3_P
- NC
- $0.2
- NC
- NC
- P43_0
- USB1_TXN
- ETH_TRX2_N
- ETH_TRX2_N
- ETH_TRX2_N
- NC
- NC
- NC
- NC
- NC
- NC
- P42_1
- USB1_RXN
- USB1_RXP
- ETH_TRX2_P
- ETH_TRX2_P
- ETH_TRX2_P
- NC
- ETH_TRX1_N
- ETH_TRX1_N
- ETH_TRX1_N
- ETH_TRX1_N
- USB_DP
- USB_DP
- USB_DP
- USB_DP
- ETH_TRX1_P
- ETH_TRX1_P
- ETH_TRX1_P
- ETH_TRX1_P
- USB_DN
- USB_DN
- USB_DN
- USB_DN
- ETH_TRX0_N
- ETH_TRX0_N
- ETH_TRX0_N
- ETH_TRX0_N
- USB_DP
- NC
- USB_DP
- USB_DP
- ETH_TRX0_P
- ETH_TRX0_P
- ETH_TRX0_P
- ETH_TRX0_P
- USB_DN
- NC
- USB_DN
- USB_DN
- LED0
- LED0
- LED_0/PHY_CFG0
- LED0
- NC
- GPIO_10
- P2_1
- GPIO1.IO[07]
- LED1
- LED1
- LED1_0/PHY_CFG0
- LED1
- NC
- P2_0
- NC
- NC
- P43_1
- NC
- RSPI1_SSL
- SPI_CS1
- RSPI1_SSL
- ECSPI2_SS0
- I2C3_SCL
- RIIC0_SCL
- I2C2_SCL
- RIIC0_SCL
- P40_2
- P3_0
- NC
- I2C3_SDA
- RIIC0_SDA
- I2C2_SDA
- RIIC0_SDA
- SD0_CLK
- SD1_CLK
- SD0_CLK
- SD2_CLK
- GPIO1.IO[14]
- P42_0
- H_GPIO_14
- P5_0
- MECH_X_Y is a mechanical hole that the hole size is X mm and padstack is Y mm.
  J15, J16 and J17 are M2.5
  J18, J19 and J27 are M1.8
  J27 is a new mechanical hol for MicroSOM rev 1.4 and newer
- SD0_CMD
- SD1_CMD
- SD0_CMD
- SD2_CMD
- NC
- P43_2
- NC
- NC
- SD0_DATA0
- SD1_DATA0
- SD0_DATA0
- SD2_DATA0
- GPIO4.IO[28]
- P43_3
- NC
- NC
- SD0_DATA1
- SD1_DATA1
- SD0_DATA1
- SD2_DATA1
- SD0_DATA2
- SD1_DATA2
- SD0_DATA2
- SD2_DATA2
- SPI_MISO
- SPI_MISO
- SPI_DQ0
- SPI_MISO
- SD0_DATA3
- SD1_DATA3
- SD0_DATA3
- SD2_DATA3
- SPI_MOSI
- SPI_MOSI
- SPI_DQ1
- SPI_MOSI
- NC
- SDI0_CD_IN
- SDIO1_CD_IN
- P8_0
- SDI0_CD_IN
- SDI2_CD_IN
- USB2_VBUS_3V3
- I2C2_SDA
- SPI_CLK
- RIIC1_SDA
- SPI_CLK
- I2C1_SDA
- SPI_CLK
- RIIC1_SDA
- SPI_CLK
- NC
- P8_1
- CAN2_RX
- I2C2_SCL
- RIIC1_SCL
- I2C1_SCL
- RIIC1_SCL
- NC
- P8_2
- CAN2_TX
- GPIO3.IO[20]
- CAN0_RX/P11_0
- NC
- NC
- NC
- P9_0
- GPIO3.IO[23]
- CAN0_TX/P10_1
- NC
- NC
- RZ_WDTOVF_PERROUT
- RZ_WDTOVF_PERROUT
- WDOG_B
- NC
- CAN1_RX/P13_0
- NC
- NC
- ON/OFF
- SD0_DEV_SEL
- ON/OFF
- SD0_DEV_SEL
- NC
- ON/OFF
- NC
- CAN1_TX/P12_1
- NC
- NC
- PMIC_EN
- PMIC_EN
- VSD_3V3
- SD0_PWR_EN
- GPIO_11
- SD0_PWR_EN
- SD2_RESET_B
- PIN -> 0.3A
